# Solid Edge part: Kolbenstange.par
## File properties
Username: bmolnar
Dokumentum tartalom típus: 0
Author: bmolnar
Last saved by: bmolnar
Revision: 88
Sűrűség: 0,000 kg/m^3
Pontosság: 0,990
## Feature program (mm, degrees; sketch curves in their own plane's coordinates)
base feature "unnamed BaseFeature 1"
sketch for "unnamed Protrusion 1" plane through (67.2, 0, 0) normal (1, 0, 0) x-axis (0, 0, 1)
  circle centre (0, 0) radius 50
extrude "unnamed Protrusion 1" add finite 23.3 along +normal
sketch for "Kihúzás_2" plane through (67.2, 0, 0) normal (1, 0, 0) x-axis (0, 0, 1)
  circle centre (0, 0) radius 50
extrude "Kihúzás_2" add finite 4.7 along -normal
thread "unnamed Thread 1"
chamfer "Letörés_1" setback 3.3  SetBackValue2 = 20 deg
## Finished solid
Body 1: solid body, 17 faces, 23 edges, 8 vertices.
  Faces by surface: plane 8, cylinder 4, torus 3, cone 2
  Edges by curve: circle 13, line 6, ellipse 2, intersection 2
Bounding box of the edges (mm; curved faces can reach further): 165.500 x 100.000 x 100.000, from (-75, -50, -50) to (90.5, 50, 50).
Cylindrical faces by radius (mm): R7 x1, R8 x1, R12.5 x1, R50 x1
Conical faces (half-angle, radius in mm at the cone's reference point): 20 deg R6.7989 x1, 60 deg R7.6 x1
Toroidal faces (ring radius, tube radius in mm): R7.4 r0.4 x2, R10.7 r1.8 x1
Planar faces by outward normal: +x 1, +z 1, -x 3, -z 1, oblique 2
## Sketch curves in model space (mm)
circle centre (67.2, 0, 0) radius 50
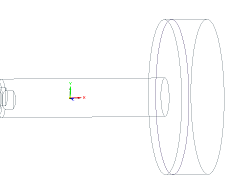
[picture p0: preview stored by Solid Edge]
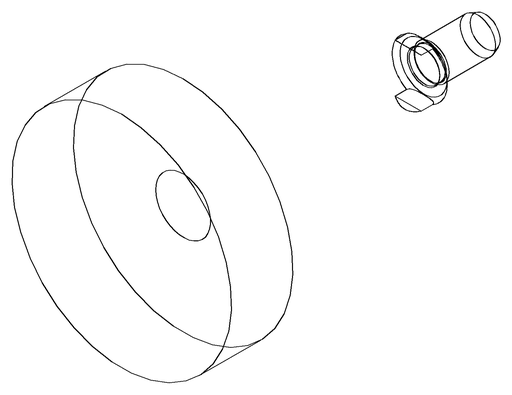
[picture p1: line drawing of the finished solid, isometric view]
